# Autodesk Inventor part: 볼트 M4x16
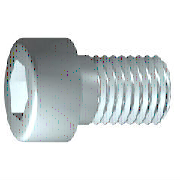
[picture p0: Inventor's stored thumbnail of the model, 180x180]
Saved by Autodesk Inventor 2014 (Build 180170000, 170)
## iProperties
IsCustomPart: 1
Created: 2012-02
Part Number: 볼트 M4x16
Material: 강철, 연강
Description: 6각머리 태핑 나사
Document SubType Name: Modeling
Standard: KS B 1003
Designer: mduedu
Standards Organization: KS
Language: ko-KR
Size Designation: M 4 x 16
Categories: <MemberInstance><Categories><Category DisplayName="조임쇠" InternalName="e4da775c-781d-43d5-af7c-5136215cf5a6" Mnemonic="FSTN"><Category DisplayName="볼트" InternalN
Density: 1 g/cm^3
Appearance: Steel
Author: mduedu
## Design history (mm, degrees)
sketch "스케치1"
  geometry: L1 (-1, 0)-(16, 0); L2 (16, 0)-(16, 2); L3 (16, 2)-(1.75, 2); L4 (1.75, 2)-(1.32, 2); L5 (1.32, 2)-(0, 2); L6 (0, 2)-(0, 3.5); L7 (0, 3.5)-(-4, 3.5); L8 (-4, 3.5)-(-4, 1.732); L9 (-4, 1.732)-(-2, 1.732); L10 (-2, 1.732)-(-1, 0); L11 (-8, 0)-(20, 0) reference; L12 (0, -0.7)-(0, 4.2) reference; L13 (1.75, 2)-(0, 2)
  constraints: 22 end point, 6 parallel, 2 collinear, 2 perpendicular, 1 horizontal, 1 point on line
  dimensions: "d1" = 14.25 distance from line of L3.end L2 (= GEL); "d2" = 0.42952 distance of L4.end L3.end (computed from GAL); "d3" = 4 distance between parallel lines of L8 L6 (= KOH); "d4" = 2 distance of L8.end L9.end (= INTI); "d5" = 60 deg angle of L10 L1; "d6" = 4 diameter of L3 L1 (= GD); "d7" = 4 diameter of L5 L1 (= BDM); "d8" = 3.4641 diameter of L9 L1 (= 1.1547 x SW); "d9" = 7 diameter of L7 L1 (= KOD); "d26" = 16 distance between parallel lines of L12 L2 (= NLG)
revolve "본체" sketch "스케치1" stored, may be unused: angle "d10" = 90 deg
sketch "스케치2"
  geometry: L1 (0, -4.9)-(0, 4.9) reference; L2 (-4.9, 0)-(4.9, 0) reference; L3 (1.732, 0)-(0.866, -1.5); L4 (0.866, -1.5)-(-0.866, -1.5); L5 (-0.866, -1.5)-(-1.732, 0); L6 (-1.732, 0)-(-0.866, 1.5); L7 (-0.866, 1.5)-(0.866, 1.5); L8 (0.866, 1.5)-(1.732, 0); 2 further points
  constraints: 12 end point, 1 coincident, 1 horizontal alignment, 1 point on line, 12 other
extrude "슬롯" join sketch "스케치2" stored distance "d11" = 10; taper "d12" = 0 deg
workplane "Work Plane1"
fillet "Fillet2" dims "d30" = 0.1 (= R)
body "Solid1"
fillet "모깎기1" dims "d17" = 0.4 (= RR)
feature "스레드" dims "d13" = 14.25 (= GEL), "d14" = 0
chamfer "모따기1" distance "d15" = 0.42941 (= -0.5 x SPD + 0.5 x GD); stored, may be unused: second distance "d16" = 0.42941 (= GUL), angle "d27" = 45 deg
other parameters: "GD" = 4 (= NND) [user parameter; used in 2 equation terms], "NLG" = 16 [user parameter; used in 1 equation term], "GEL" = 14.25 [user parameter; used in 2 equation terms], "KOD" = 7 [user parameter; used in 1 equation term], "KOH" = 4 [user parameter; used in 1 equation term], "INTI" = 2 [user parameter; used in 1 equation term], "GAL" = 0.42941 (= 0.61345 x PTC) [user parameter; used in 1 equation term], "GUL" = 0.42941 (= 0.61345 x PTC) [user parameter; used in 1 equation term], "BDM" = 4 (= NND) [user parameter; used in 1 equation term], "SW" = 3 [user parameter; used in 2 equation terms], "RR" = 0.4 [user parameter; used in 1 equation term], "SPD" = 3.14117 (= NND - 1.2269 x PTC) [user parameter; used in 1 equation term], "d19" = 0, "d28" = 0, "d29" = 0, "R" = 0.1 [user parameter; used in 1 equation term], "PHH" = 0.2 [user parameter], "GD1" = 3.14117 (= THREADDIA - 1.2269 x PTC) [user parameter], "THREADDIA" = 4 [user parameter; used in 1 equation term], "FAWI" = 45 deg [user parameter], "TPU" = 14.28571 (computed from PTC) [user parameter], "PTC" = 0.7 [user parameter; used in 5 equation terms], "NND" = 4 [user parameter; used in 3 equation terms], "TOA" = 30 deg [user parameter], "E0" = 3.465 (= 1.155 x SW) [user parameter]
